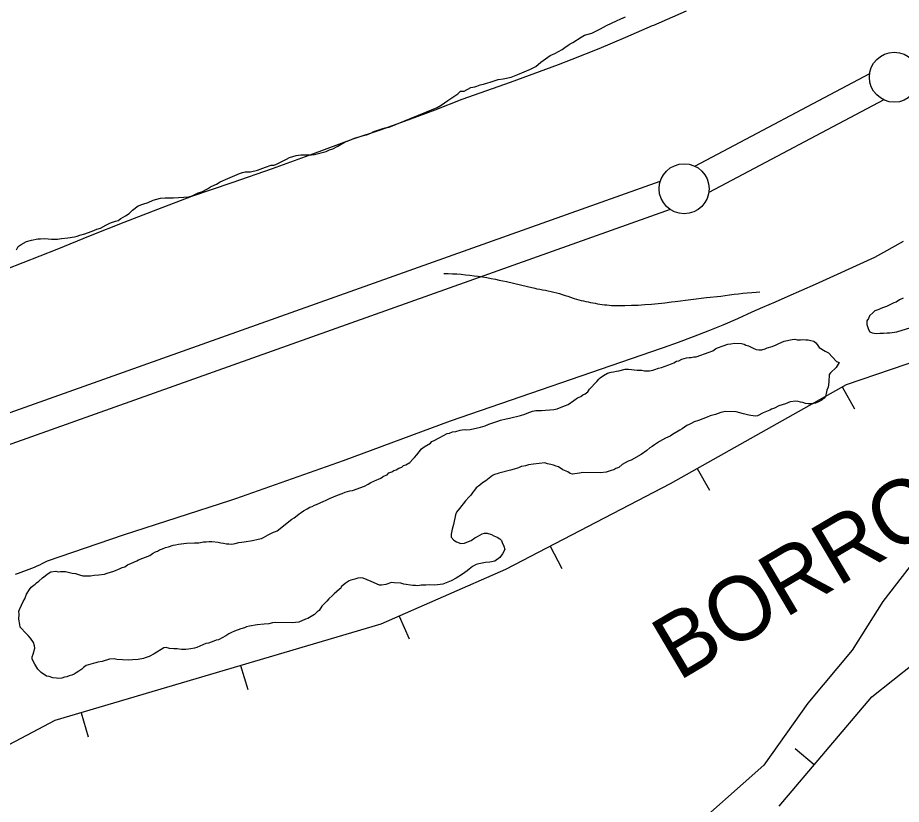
# Model space of a CAD drawing. Extents: x 3177385 to 3215275, y 903885 to 929304.
# Drawn here: x 3189739 to 3190624, y 914509 to 915297 of the extents above; entities that cross this region are included whole.
import ezdxf

# ---------------------------------------------------------------- set-up
doc = ezdxf.new("R2010")
doc.units = 0
for name, color, linetype in [('V-BORW-IDEN', 7, 'Continuous'), ('V-BORW-LINE', 7, 'Continuous'), ('V-LEVE-TOET', 7, 'Continuous'), ('V-ROAD-CNTR', 7, 'Continuous'), ('V-SITE-VEGE', 7, 'Continuous'), ('V-SURV-LINE', 7, 'Continuous')]:
    doc.layers.add(name, color=color, linetype=linetype)

msp = doc.modelspace()

# ---------------------------------------------------------------- linework, layer by layer
at = {"layer": 'V-BORW-LINE'}
for p, q in [((3190564.49, 914926.83), (3190576.73, 914905.04)), ((3190419.23, 914845.25), (3190431.48, 914823.45)), ((3190271.97, 914767.37), (3190283.52, 914745.2)), ((3190120.81, 914697.52), (3190130.83, 914674.61)), ((3189961.91, 914647.9), (3189969.01, 914623.92)), ((3189802.16, 914600.63), (3189809.25, 914576.66)), ((3190536.42, 914548.38), (3190517.34, 914564.53))]:
    msp.add_line(p, q, dxfattribs=at)
for points in [[(3190748.57, 914990.48), (3190568.34, 914929)], [(3190568.34, 914929), (3190392.06, 914829.99)], [(3190392.06, 914829.99), (3190227.21, 914744.03)], [(3190227.21, 914744.03), (3190102.37, 914689.45)], [(3190594.21, 914616.62), (3190741.37, 914733.35)], [(3190102.37, 914689.45), (3189775.91, 914592.86)], [(3190501.38, 914506.99), (3190594.21, 914616.62)], [(3189775.91, 914592.86), (3189620.83, 914511.01)]]:
    msp.add_lwpolyline(points, dxfattribs=at)
at = {"layer": 'V-LEVE-TOET'}
for points in [[(3190183.93, 915215.18), (3190232.27, 915232.1), (3190280.31, 915249.84), (3190294.14, 915255.12), (3190294.14, 915255.12), (3190321.11, 915265.82), (3190347.88, 915276.99), (3190374.46, 915288.62), (3190375.8, 915289.22), (3190375.8, 915289.22), (3190408.65, 915303.58)], [(3189692.69, 915031.46), (3189778.16, 915064.86), (3189811.73, 915078.39), (3189845.39, 915091.73), (3189879.12, 915104.86), (3189912.93, 915117.79), (3189953.55, 915131.54), (3189994.03, 915145.71), (3190034.35, 915160.3), (3190074.53, 915175.31), (3190102.16, 915184.47), (3190129.62, 915194.17), (3190156.88, 915204.41), (3190183.93, 915215.18)], [(3190625.46, 915072.54), (3190605.93, 915061.61), (3190596.66, 915056.58), (3190596.66, 915056.58), (3190537.46, 915029.52), (3190510.01, 915017.39), (3190510.01, 915017.39), (3190497.23, 915011.91), (3190484.49, 915006.36), (3190474.04, 915001.74), (3190459.48, 914995.18), (3190444.81, 914988.86), (3190430.03, 914982.79), (3190415.15, 914976.97), (3190400.18, 914971.41), (3190385.11, 914966.1), (3190383.24, 914965.46), (3190383.24, 914965.46), (3190171.84, 914892.59), (3190171.84, 914892.59), (3190064.64, 914852.88), (3189956.76, 914815.01), (3189951.87, 914813.34), (3189951.87, 914813.34), (3189844.24, 914778.32), (3189768.16, 914752.31), (3189765.58, 914751.02), (3189762.99, 914749.76), (3189760.37, 914748.54), (3189757.74, 914747.36), (3189755.1, 914746.21), (3189752.44, 914745.1), (3189749.77, 914744.02), (3189747.09, 914742.99), (3189744.39, 914741.98), (3189741.68, 914741.02), (3189738.97, 914740.09), (3189736.24, 914739.2)]]:
    msp.add_lwpolyline(points, dxfattribs=at)
at = {"layer": 'V-ROAD-CNTR'}
msp.add_lwpolyline([(3190165.31, 915040.53), (3190169.67, 915040.42), (3190174.03, 915040.24), (3190178.38, 915039.99), (3190182.72, 915039.67), (3190187.05, 915039.28), (3190191.38, 915038.83), (3190195.69, 915038.3), (3190200, 915037.71), (3190204.29, 915037.05), (3190208.56, 915036.32), (3190212.82, 915035.53), (3190217.07, 915034.67), (3190221.04, 915033.8), (3190228.15, 915032.39), (3190235.24, 915030.87), (3190242.33, 915029.25), (3190249.4, 915027.52), (3190256.44, 915025.69), (3190258.6, 915025.11), (3190258.6, 915025.11), (3190261.47, 915024.67), (3190264.33, 915024.19), (3190267.18, 915023.65), (3190270.03, 915023.07), (3190272.86, 915022.44), (3190275.69, 915021.77), (3190278.5, 915021.05), (3190281.31, 915020.28), (3190284.1, 915019.46), (3190286.88, 915018.6), (3190289.65, 915017.69), (3190292.4, 915016.73), (3190295.14, 915015.73), (3190296.14, 915015.35), (3190296.14, 915015.35), (3190298.41, 915014.71), (3190300.68, 915014.1), (3190302.97, 915013.52), (3190305.27, 915012.97), (3190307.57, 915012.44), (3190309.89, 915011.94), (3190312.21, 915011.47), (3190314.54, 915011.03), (3190316.87, 915010.62), (3190319.21, 915010.23), (3190321.56, 915009.88), (3190323.91, 915009.55), (3190326.26, 915009.25), (3190328.62, 915008.99), (3190330.98, 915008.75), (3190333.33, 915008.54), (3190340.02, 915008.46), (3190346.72, 915008.49), (3190353.42, 915008.64), (3190360.11, 915008.91), (3190366.8, 915009.29), (3190373.48, 915009.79), (3190380.14, 915010.4), (3190386.8, 915011.14), (3190393.45, 915011.99), (3190397.18, 915012.51), (3190397.18, 915012.51), (3190412.79, 915014.54), (3190428.42, 915016.31), (3190442.92, 915017.72), (3190447.31, 915018.44), (3190451.7, 915019.11), (3190456.11, 915019.71), (3190460.53, 915020.25), (3190464.96, 915020.73), (3190469.4, 915021.15), (3190473.85, 915021.51), (3190478.3, 915021.82), (3190481.83, 915022.01)], dxfattribs=at)
at = {"layer": 'V-SITE-VEGE'}
for points in [[(3189850.14, 915100.66), (3189853.64, 915104.01), (3189859.44, 915108.08), (3189864.05, 915109.89), (3189869.43, 915111.68), (3189874.43, 915113.86), (3189881.71, 915115.99), (3189886.3, 915116.28), (3189894.68, 915116.1), (3189909.95, 915117.3), (3189913.4, 915118.37), (3189919.56, 915121.28), (3189923.01, 915122.36), (3189928.79, 915125.28), (3189931.88, 915127.12), (3189935.35, 915128.95), (3189937.66, 915130.05), (3189941.52, 915132.25), (3189949.21, 915135.52), (3189960.75, 915140.61), (3189963.82, 915141.69), (3189966.51, 915142.39), (3189971.84, 915142.28), (3189978.74, 915144.04), (3189986.8, 915146.91), (3189992.57, 915149.08), (3189995.23, 915149.02), (3189997.15, 915149.74), (3190007.93, 915154.85), (3190011.02, 915156.69), (3190017.54, 915158.46), (3190022.13, 915159.12), (3190032.8, 915159.27), (3190035.86, 915159.59), (3190047.74, 915162.77), (3190050.82, 915164.22), (3190054.27, 915165.3), (3190059.28, 915167.86), (3190062.76, 915170.07), (3190066.62, 915172.27), (3190069.69, 915173.35), (3190075.84, 915175.89), (3190085.05, 915178.74), (3190088.11, 915179.44), (3190092.34, 915180.87), (3190095.42, 915182.71), (3190097.35, 915183.43), (3190103.48, 915185.21), (3190106.55, 915186.29), (3190110.76, 915186.96), (3190147.29, 915202.02), (3190158.75, 915206.81), (3190162.79, 915208.86), (3190169.51, 915213.62), (3190179.61, 915220.42), (3190182.29, 915223.14), (3190185.67, 915223.15), (3190192.4, 915226.57), (3190196.45, 915227.26), (3190198.47, 915227.95), (3190201.84, 915229.32), (3190205.21, 915230.01), (3190207.23, 915230.69), (3190211.95, 915232.07), (3190220.04, 915234.81), (3190224.76, 915235.51), (3190232.85, 915236.9), (3190239.59, 915239.64), (3190252.39, 915245.11), (3190257.77, 915247.84), (3190262.48, 915251.92), (3190271.89, 915258.71), (3190276.61, 915260.76), (3190284.01, 915264.85), (3190286.7, 915266.89), (3190290.07, 915268.94), (3190292.09, 915270.3), (3190294.78, 915271.66), (3190302.85, 915277.1), (3190306.22, 915279.15), (3190313.63, 915281.21), (3190317.67, 915283.26), (3190322.38, 915285.31), (3190328.44, 915288.72), (3190338.55, 915293.49), (3190342.59, 915295.54), (3190347.3, 915297.59)], [(3189737.31, 915064.19), (3189739.29, 915067.58), (3189741.99, 915069.42), (3189747.39, 915072.36), (3189752.37, 915073.77), (3189758.89, 915075.16), (3189761.55, 915075.1), (3189765.75, 915075.4), (3189772.6, 915074.87), (3189778.69, 915074.74), (3189782.52, 915075.42), (3189789.01, 915076.04), (3189795.51, 915077.05), (3189798.19, 915077.75), (3189800.89, 915078.84), (3189805.87, 915080.26), (3189808.56, 915081.34), (3189813.17, 915082.77), (3189817.79, 915084.96), (3189821.62, 915086.02), (3189827.02, 915088.95), (3189831.64, 915091.14), (3189836.63, 915092.94), (3189839.31, 915093.65), (3189842.02, 915095.5), (3189846.65, 915098.06), (3189850.14, 915100.66)], [(3190625.36, 915015.79), (3190621.89, 915013.96), (3190618.42, 915011.74), (3190616.11, 915011.03), (3190611.49, 915008.84), (3190608.8, 915007.37), (3190605.73, 915006.3), (3190603.04, 915005.59), (3190601.11, 915004.49), (3190597.27, 915003.05), (3190595.33, 915001.56), (3190591.83, 914998.21), (3190590.63, 914995.57), (3190589.05, 914992.93), (3190588.98, 914989.5), (3190590.78, 914984.51), (3190592.25, 914982.19), (3190594.51, 914981), (3190598.31, 914980.54), (3190602.13, 914980.84), (3190605.94, 914980.75), (3190609.38, 914981.06), (3190612.05, 914981.01), (3190619.31, 914982), (3190633.12, 914986.28)], [(3190309.69, 914921.89), (3190311.28, 914924.53), (3190318.68, 914932.37), (3190320.64, 914934.62), (3190322.19, 914936.11), (3190325.29, 914938.33), (3190329.53, 914940.53), (3190332.98, 914941.6), (3190335.28, 914941.93), (3190338.34, 914942.63), (3190340.63, 914942.96), (3190347.15, 914944.73), (3190350.58, 914944.65), (3190358.95, 914943.71), (3190363.9, 914943.61), (3190366.56, 914943.17), (3190371.51, 914943.06), (3190374.95, 914943.75), (3190376.87, 914944.47), (3190380.33, 914945.54), (3190383.39, 914946.24), (3190390.69, 914949.13), (3190395.69, 914950.93), (3190398.39, 914952.78), (3190400.69, 914953.11), (3190403.77, 914954.57), (3190408.37, 914956), (3190411.05, 914956.32), (3190413.33, 914956.27), (3190416.01, 914956.98), (3190418.3, 914956.93), (3190431.36, 914961.61), (3190434.82, 914963.06), (3190437.53, 914964.9), (3190439.46, 914966.01), (3190445.22, 914968.17), (3190449.82, 914969.6), (3190452.88, 914969.91), (3190456.7, 914970.6), (3190463.56, 914970.45), (3190466.21, 914969.63), (3190468.1, 914968.83), (3190470.75, 914968.01), (3190475.27, 914965.63), (3190478.3, 914964.42), (3190480.96, 914963.98), (3190484, 914963.92), (3190487.46, 914964.98), (3190489.39, 914966.09), (3190494.37, 914967.51), (3190498.21, 914968.95), (3190500.91, 914970.42), (3190506.29, 914972.59), (3190514.34, 914974.32), (3190517.01, 914974.65), (3190519.29, 914974.22), (3190522.72, 914974.15), (3190525.01, 914974.48), (3190528.05, 914974.03), (3190530.33, 914973.98), (3190532.99, 914973.55), (3190536.02, 914972.72), (3190537.9, 914971.15), (3190539.38, 914969.22), (3190541.23, 914966.51), (3190547.24, 914962.57), (3190550.64, 914960.97), (3190558.84, 914952.41)], [(3190558.84, 914952.41), (3190561.48, 914951.21), (3190558.33, 914946.33), (3190552.88, 914941.1), (3190551.32, 914939.23), (3190551.16, 914932), (3190550.72, 914928.96), (3190550.29, 914926.68), (3190549.08, 914923.65), (3190548.25, 914920.24), (3190547.81, 914917.58), (3190546.25, 914915.71), (3190543.53, 914913.48), (3190540.83, 914912.02), (3190537.75, 914910.56), (3190534.31, 914909.87), (3190530.5, 914909.95), (3190527.84, 914910.39), (3190525.19, 914911.21), (3190522.53, 914911.64), (3190520.26, 914912.45), (3190517.97, 914912.5), (3190512.24, 914911.86), (3190507.63, 914910.06), (3190504.18, 914908.98), (3190501.11, 914907.91), (3190496.48, 914905.72), (3190493.8, 914904.63), (3190491.86, 914903.53), (3190485.33, 914901), (3190479.55, 914898.08), (3190477.26, 914897.74), (3190470.8, 914898.64), (3190465.49, 914899.9), (3190458.29, 914901.96), (3190447.63, 914902.18), (3190443.03, 914901.14), (3190437.66, 914899.35), (3190432.29, 914897.94), (3190429.21, 914896.48), (3190420.37, 914893.24), (3190416.15, 914891.8), (3190413.07, 914890.35), (3190411.14, 914889.24), (3190408.83, 914888.15), (3190404.19, 914884.82), (3190401.88, 914883.72), (3190394.54, 914879.3), (3190392.22, 914877.45), (3190387.6, 914875.64), (3190381.44, 914872.34), (3190376.41, 914869.02), (3190374.08, 914867.16), (3190371.77, 914866.07), (3190368.66, 914863.09), (3190363.25, 914859.39), (3190353.21, 914853.51), (3190350.14, 914852.43), (3190343.97, 914849.13), (3190340.86, 914846.15), (3190337.79, 914845.07), (3190335.86, 914843.97), (3190333.18, 914843.26), (3190328.18, 914841.46), (3190322.45, 914840.82), (3190304.55, 914841.2), (3190301.48, 914840.51), (3190294.22, 914839.52), (3190291.95, 914840.33), (3190289.7, 914841.9), (3190284.79, 914843.91), (3190280.28, 914847.06), (3190278, 914847.48), (3190275.36, 914848.68), (3190272.7, 914849.12), (3190269.29, 914849.96), (3190266.64, 914850.78), (3190255.18, 914849.5), (3190250.21, 914848.84), (3190247.14, 914847.76), (3190243.69, 914847.07), (3190242.93, 914847.09), (3190240.24, 914846), (3190236.02, 914844.57), (3190232.18, 914843.51), (3190220.69, 914840.7), (3190218.77, 914839.98), (3190216.08, 914839.28), (3190215.69, 914838.9), (3190214.15, 914838.17), (3190207.57, 914832.98), (3190204.09, 914830.76), (3190201.37, 914828.54), (3190197.89, 914825.94), (3190196.31, 914823.69), (3190194.36, 914821.44), (3190192.39, 914818.44), (3190190.84, 914816.95), (3190187.32, 914812.83), (3190181.06, 914805.34), (3190178.31, 914801.59)], [(3189907.81, 914770.38), (3189915.82, 914770.97), (3189920.02, 914770.88), (3189924.61, 914771.93), (3189927.28, 914771.87), (3189930.34, 914772.19), (3189933, 914772.13), (3189939.47, 914771.61), (3189942.12, 914770.79), (3189944.78, 914770.35), (3189947.82, 914769.91), (3189950.1, 914769.86), (3189953.14, 914769.41), (3189956.59, 914770.1), (3189960.04, 914771.17), (3189965.39, 914771.82), (3189973.8, 914773.16), (3189979.55, 914774.57), (3189982.99, 914775.26), (3189984.91, 914775.98), (3189989.55, 914778.93), (3189993.01, 914780.38), (3189994.94, 914781.48), (3189996.86, 914782.2), (3189998.4, 914782.93), (3190013.13, 914794.43), (3190015.45, 914795.91), (3190018.55, 914798.13), (3190020.49, 914799.99), (3190022.42, 914801.1), (3190024.75, 914802.95), (3190028.6, 914804.78), (3190031.3, 914806.62), (3190033.61, 914807.34), (3190035.92, 914808.43), (3190037.84, 914809.15), (3190045.15, 914812.43), (3190047.07, 914813.15), (3190050.93, 914815.35), (3190059, 914818.61), (3190063.61, 914820.04), (3190066.69, 914821.5), (3190071.29, 914822.92), (3190073.96, 914823.25), (3190085.87, 914827.57), (3190089.72, 914829.39), (3190092.43, 914831.24), (3190098.2, 914833.78), (3190100.12, 914834.5), (3190102.43, 914835.6), (3190105.14, 914837.45), (3190108.6, 914838.9), (3190110.54, 914840.76), (3190113.23, 914841.85), (3190115.55, 914843.32), (3190117.85, 914844.04), (3190120.55, 914845.5), (3190123.24, 914846.59), (3190125.18, 914848.07), (3190127.48, 914848.79), (3190131.35, 914851.37), (3190134.47, 914854.73), (3190136.03, 914856.22), (3190138.37, 914858.85), (3190143.07, 914864.84), (3190145.79, 914867.07), (3190151.96, 914870.75), (3190153.52, 914872.24), (3190155.83, 914873.34), (3190161.61, 914876.27), (3190168.94, 914880.3), (3190171.23, 914880.63), (3190174.31, 914882.09), (3190177.37, 914882.41), (3190181.96, 914883.45), (3190185.79, 914884.13), (3190188.45, 914884.08), (3190191.89, 914884.38), (3190202.22, 914886.45), (3190206.83, 914887.88), (3190210.68, 914889.7), (3190219.5, 914892.56), (3190222.2, 914893.65), (3190227.94, 914895.05), (3190231.39, 914895.74), (3190242.11, 914898.18), (3190246.71, 914899.6), (3190249.02, 914900.7), (3190254.4, 914902.49), (3190257.46, 914903.19), (3190263.19, 914903.45), (3190275.78, 914904.32), (3190278.85, 914905.02), (3190284.61, 914907.18), (3190289.99, 914909.35), (3190295.8, 914913.42), (3190299.28, 914916.02), (3190302.74, 914917.47), (3190304.68, 914918.95), (3190306.99, 914920.05), (3190309.69, 914921.89)], [(3190178.31, 914801.59), (3190177.11, 914798.95), (3190175, 914789.08), (3190173.76, 914784.53), (3190172.89, 914779.6), (3190172.82, 914776.55), (3190175.43, 914773.45), (3190178.06, 914771.86), (3190182.6, 914770.24), (3190186.03, 914770.55), (3190190.26, 914771.99), (3190192.95, 914773.07), (3190196.44, 914775.67), (3190199.13, 914777.13), (3190201.45, 914778.61), (3190203.76, 914779.7), (3190206.06, 914780.41), (3190208.73, 914780.36), (3190213.28, 914779.12), (3190215.54, 914777.93), (3190218.94, 914776.33), (3190221.57, 914774.75), (3190223.06, 914773.19), (3190223.78, 914771.27), (3190225.61, 914767.42), (3190226.68, 914763.97), (3190224.3, 914759.83), (3190221.55, 914756.07), (3190216.52, 914752.37), (3190211.54, 914751.33), (3190207.34, 914751.04), (3190200.45, 914749.66), (3190197.77, 914748.96), (3190194.3, 914747.13), (3190190.82, 914744.53), (3190188.87, 914742.67), (3190184.23, 914739.34), (3190177.66, 914735.29), (3190172.65, 914732.72), (3190169.57, 914731.26), (3190164.58, 914729.46), (3190156.56, 914728.49), (3190150.84, 914728.61), (3190147.41, 914728.31), (3190142.83, 914728.4), (3190139.39, 914727.71), (3190137.11, 914728.14), (3190134.44, 914728.2), (3190125.33, 914729.54), (3190122.29, 914730.37), (3190115.83, 914730.88), (3190113.16, 914730.94), (3190107.4, 914729.16), (3190103.2, 914728.49), (3190100.91, 914728.53), (3190092.6, 914732.14), (3190084.67, 914735.36), (3190082.01, 914735.8), (3190079.33, 914735.47), (3190076.26, 914734.4), (3190072.43, 914733.34), (3190070.51, 914732.61), (3190066.64, 914730.03), (3190062.76, 914726.68), (3190062.35, 914725.54), (3190060.81, 914724.43), (3190055.75, 914719.59), (3190053.81, 914718.1), (3190050.31, 914714.75), (3190048.36, 914712.5), (3190043.29, 914707.27), (3190040.53, 914703.14), (3190038.6, 914701.66), (3190035.87, 914699.05), (3190029.31, 914694.99), (3190027.01, 914694.28), (3190020.08, 914691.38), (3190013.59, 914690.76), (3189996.83, 914691.11), (3189993.77, 914690.8), (3189990.32, 914689.73), (3189985.36, 914689.45), (3189978.49, 914688.84), (3189970.83, 914687.47), (3189967.77, 914686.78), (3189965.84, 914685.68), (3189962.01, 914684.61), (3189955.86, 914682.46), (3189952.78, 914681), (3189950.08, 914679.53), (3189947, 914677.69), (3189939.67, 914673.65), (3189937.37, 914673.32), (3189935.06, 914672.23), (3189929.69, 914670.44), (3189927.02, 914670.12), (3189918.16, 914666.11), (3189915.86, 914665.4), (3189912.04, 914664.72), (3189907.07, 914664.06), (3189902.88, 914664.15)], [(3189902.88, 914664.15), (3189898.32, 914664.63), (3189894.88, 914664.7), (3189890.7, 914665.17), (3189887.29, 914666.01), (3189885, 914665.67), (3189875.34, 914659.78), (3189870.33, 914656.84), (3189866.49, 914655.78), (3189864.57, 914655.06), (3189859.21, 914654.03), (3189853.49, 914653.77), (3189850.05, 914653.46), (3189843.58, 914653.6), (3189837.87, 914654.1), (3189835.21, 914654.54), (3189830.63, 914654.25), (3189823.35, 914652.12), (3189818.76, 914651.46), (3189816.84, 914650.74), (3189814.15, 914650.03), (3189807.25, 914647.89), (3189804.54, 914646.04), (3189802.98, 914644.17), (3189799.89, 914642.33), (3189797.18, 914640.48), (3189795.25, 914639.38), (3189792.94, 914638.29), (3189790.26, 914637.58), (3189787.95, 914636.49), (3189785.66, 914636.16), (3189782.97, 914635.45), (3189779.92, 914635.13), (3189777.63, 914635.18), (3189773.83, 914635.65), (3189770.04, 914636.87), (3189767.39, 914637.31), (3189762.13, 914640.85), (3189758.77, 914644.35), (3189755.83, 914649.37), (3189753.27, 914654.38), (3189753.32, 914656.66), (3189754.13, 914659.31), (3189755.79, 914665.38), (3189755.46, 914667.67), (3189754.39, 914671.12), (3189751.43, 914675.38), (3189749.2, 914678.09), (3189747.32, 914679.66), (3189740.99, 914686.27), (3189740.66, 914688.95), (3189739.64, 914694.3), (3189740.12, 914699.25), (3189739.8, 914701.92), (3189740.61, 914704.19), (3189742.6, 914708.35), (3189744.21, 914712.12), (3189745.79, 914714.75), (3189747.41, 914719.29), (3189750.56, 914724.18), (3189752.14, 914726.43), (3189756.01, 914729.4), (3189757.57, 914730.89), (3189759.88, 914732.37), (3189763.38, 914735.72), (3189769.2, 914740.17), (3189771.9, 914741.64), (3189776.86, 914742.3), (3189779.14, 914741.87), (3189781.44, 914742.2), (3189786.39, 914742.09), (3189790.56, 914741.24), (3189793.21, 914740.42), (3189796.63, 914739.97), (3189800.42, 914738.75), (3189803.83, 914737.91), (3189811.45, 914737.75), (3189815.27, 914738.43), (3189819.86, 914738.71), (3189825.59, 914739.35), (3189828.28, 914740.44), (3189834.8, 914742.59), (3189841.34, 914745.12), (3189843.26, 914746.22), (3189845.95, 914746.92), (3189848.66, 914748.77), (3189852.5, 914750.59), (3189857.89, 914752.77), (3189859.81, 914753.87), (3189870.96, 914758.21), (3189873.67, 914760.05), (3189876.76, 914761.89), (3189878.68, 914762.61), (3189880.61, 914763.72), (3189883.68, 914764.8), (3189886.76, 914766.25), (3189889.82, 914766.95), (3189894.43, 914768.38), (3189896.72, 914768.71), (3189899.78, 914769.41), (3189907.81, 914770.38)], [(3190649.5, 914769.48), (3190605.26, 914711.95), (3190574.3, 914663.26), (3190530.07, 914610.15), (3190485.84, 914548.19), (3190406.22, 914477.37)]]:
    msp.add_lwpolyline(points, dxfattribs=at)
at = {"layer": 'V-SURV-LINE'}
for points in [[(3190416.72, 915147.98), (3190591.97, 915240.87)], [(3190606, 915214.35), (3190430.75, 915121.47)], [(3188029.3, 914295.9), (3190382.23, 915132.81)], [(3190392.28, 915104.54), (3188039.34, 914267.63)]]:
    msp.add_lwpolyline(points, dxfattribs=at)
for centre in [(3190616.65, 915236.97), (3190406.07, 915125.37)]:
    msp.add_circle(centre, 25, dxfattribs=at)

# ---------------------------------------------------------------- texts
at = {"layer": 'V-BORW-IDEN'}
msp.add_text('BORROW PIT', height=64, rotation=30.61721, dxfattribs=at).set_placement((3190400.51, 914631.88))

doc.saveas('drawing.dxf')
